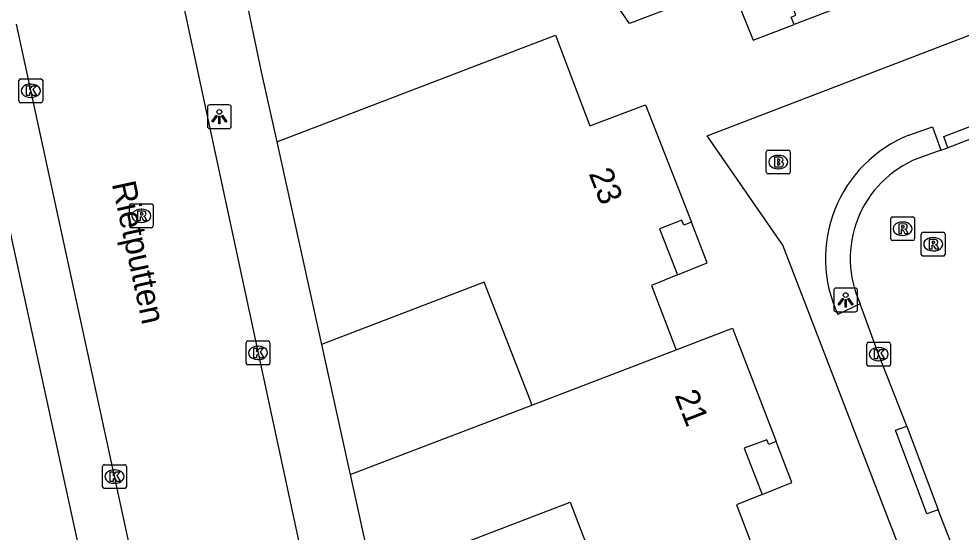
# Model space of a CAD drawing. Extents: x 159265 to 160143, y 383413 to 384319.
# Drawn here: x 159406.32 to 159445.84, y 383665.08 to 383686.61 of the extents above; entities that cross this region are included whole.
import ezdxf

# ---------------------------------------------------------------- set-up
doc = ezdxf.new("R2010")
doc.units = 0
for name, color, linetype in [('IMGEO_Brandkraan', 7, 'Continuous'), ('IMGEO_Hek', 7, 'Continuous'), ('IMGEO_Kolk', 7, 'Continuous'), ('IMGEO_Lichtpunt', 7, 'Continuous'), ('IMGEO_Openbare_ruimte_label', 7, 'Continuous'), ('IMGEO_Pand', 7, 'Continuous'), ('IMGEO_Pand_nummerreeks', 7, 'Continuous'), ('IMGEO_Pand_overbouw', 7, 'Continuous'), ('IMGEO_Rijbaan_lokaal_open', 7, 'Continuous'), ('IMGEO_Rioolput', 7, 'Continuous'), ('IMGEO_Voetpad_open', 7, 'Continuous')]:
    doc.layers.add(name, color=color, linetype=linetype)

msp = doc.modelspace()

# ---------------------------------------------------------------- linework, layer by layer
at = {"layer": 'IMGEO_Brandkraan'}
for p, q in [((159437.67, 383680.177), (159437.67, 383681.029)), ((159437.745, 383681.103), (159438.597, 383681.103)), ((159438.671, 383681.029), (159438.671, 383680.177)), ((159438.158, 383680.883), (159438.183, 383680.883)), ((159438.181, 383680.323), (159438.156, 383680.323)), ((159438.597, 383680.103), (159437.745, 383680.103))]:
    msp.add_line(p, q, dxfattribs=at)
for points in [[(159437.67, 383680.177), (159437.67, 383681.029)], [(159437.745, 383681.103), (159438.597, 383681.103)], [(159438.671, 383681.029), (159438.671, 383680.177)], [(159438.018, 383680.803), (159438.018, 383680.403), (159438.231, 383680.403)], [(159438.249, 383680.803), (159438.018, 383680.803)], [(159438.197, 383680.722), (159438.143, 383680.722), (159438.143, 383680.646)], [(159438.143, 383680.646), (159438.196, 383680.646)], [(159438.205, 383680.57), (159438.143, 383680.57), (159438.143, 383680.489)], [(159438.143, 383680.489), (159438.205, 383680.489)], [(159438.597, 383680.103), (159437.745, 383680.103)]]:
    msp.add_lwpolyline(points, dxfattribs=at)
for centre, radius, start, end in [((159437.747, 383681.027), 0.0765, 91.552, 178.448), ((159437.747, 383681.027), 0.0765, 91.552, 178.448), ((159438.595, 383681.027), 0.0765, 1.552, 88.448), ((159438.595, 383681.027), 0.0765, 1.552, 88.448), ((159438.198, 383680.684), 0.0379, 267.8285, 90.9355), ((159438.206, 383680.529), 0.0404, 269.8759, 90.5077), ((159438.253, 383680.658), 0.145, 59.4692, 91.5367), ((159438.278, 383680.705), 0.0922, 285.5137, 58.1501), ((159438.283, 383680.513), 0.105, 301.3115, 78.989), ((159437.747, 383680.179), 0.0765, 181.552, 268.448), ((159437.747, 383680.179), 0.0765, 181.552, 268.448), ((159438.237, 383680.654), 0.251, 268.6676, 293.5347), ((159438.595, 383680.179), 0.0765, 271.552, 358.448), ((159438.595, 383680.179), 0.0765, 271.552, 358.448)]:
    msp.add_arc(centre, radius, start, end, dxfattribs=at)
for centre, major_axis, ratio, start_param, end_param in [((159438.157, 383680.603), (-0.387, 0.002), 0.722429, 4.712389, 7.853982), ((159438.182, 383680.603), (-0.39, 0.002), 0.717154, 1.570796, 4.712389)]:
    msp.add_ellipse(centre, major_axis=major_axis, ratio=ratio, start_param=start_param, end_param=end_param, dxfattribs=at)
at = {"layer": 'IMGEO_Hek'}
msp.add_lwpolyline([(159419.007, 383672.947), (159420.173, 383667.674)], dxfattribs=at)
at = {"layer": 'IMGEO_Kolk'}
for p, q in [((159406.395, 383684.094), (159407.247, 383684.094)), ((159406.32, 383683.168), (159406.32, 383684.02)), ((159406.808, 383683.874), (159406.833, 383683.874)), ((159407.321, 383684.02), (159407.321, 383683.168)), ((159406.831, 383683.314), (159406.806, 383683.314)), ((159407.247, 383683.094), (159406.395, 383683.094)), ((159415.85, 383672.171), (159415.85, 383673.023)), ((159415.925, 383673.097), (159416.777, 383673.097)), ((159416.851, 383673.023), (159416.851, 383672.171)), ((159441.957, 383673.043), (159442.809, 383673.043)), ((159416.338, 383672.877), (159416.363, 383672.877)), ((159441.882, 383672.117), (159441.882, 383672.969)), ((159442.37, 383672.823), (159442.395, 383672.823)), ((159442.883, 383672.969), (159442.883, 383672.117)), ((159416.361, 383672.317), (159416.336, 383672.317)), ((159442.393, 383672.263), (159442.368, 383672.263)), ((159416.777, 383672.097), (159415.925, 383672.097)), ((159442.809, 383672.043), (159441.957, 383672.043)), ((159409.907, 383667.908), (159410.759, 383667.908)), ((159409.832, 383666.982), (159409.832, 383667.834)), ((159410.32, 383667.688), (159410.345, 383667.688)), ((159410.833, 383667.834), (159410.833, 383666.982)), ((159410.343, 383667.128), (159410.318, 383667.128)), ((159410.759, 383666.908), (159409.907, 383666.908))]:
    msp.add_line(p, q, dxfattribs=at)
for points in [[(159406.395, 383684.094), (159407.247, 383684.094)], [(159406.32, 383683.168), (159406.32, 383684.02)], [(159406.641, 383683.794), (159406.764, 383683.794), (159406.764, 383683.643), (159406.894, 383683.794), (159407.058, 383683.794), (159406.912, 383683.643), (159407.065, 383683.394), (159406.913, 383683.394), (159406.828, 383683.558), (159406.764, 383683.491), (159406.764, 383683.394), (159406.641, 383683.394), (159406.641, 383683.794)], [(159407.321, 383684.02), (159407.321, 383683.168)], [(159407.247, 383683.094), (159406.395, 383683.094)], [(159415.85, 383672.171), (159415.85, 383673.023)], [(159415.925, 383673.097), (159416.777, 383673.097)], [(159416.851, 383673.023), (159416.851, 383672.171)], [(159441.957, 383673.043), (159442.809, 383673.043)], [(159416.171, 383672.797), (159416.294, 383672.797), (159416.294, 383672.646), (159416.424, 383672.797), (159416.588, 383672.797), (159416.442, 383672.646), (159416.595, 383672.397), (159416.443, 383672.397), (159416.358, 383672.561), (159416.294, 383672.494), (159416.294, 383672.397), (159416.171, 383672.397), (159416.171, 383672.797)], [(159441.882, 383672.117), (159441.882, 383672.969)], [(159442.203, 383672.743), (159442.326, 383672.743), (159442.326, 383672.592), (159442.456, 383672.743), (159442.62, 383672.743), (159442.474, 383672.592), (159442.627, 383672.343), (159442.475, 383672.343), (159442.39, 383672.507), (159442.326, 383672.44), (159442.326, 383672.343), (159442.203, 383672.343), (159442.203, 383672.743)], [(159442.883, 383672.969), (159442.883, 383672.117)], [(159416.777, 383672.097), (159415.925, 383672.097)], [(159442.809, 383672.043), (159441.957, 383672.043)], [(159409.907, 383667.908), (159410.759, 383667.908)], [(159409.832, 383666.982), (159409.832, 383667.834)], [(159410.153, 383667.608), (159410.276, 383667.608), (159410.276, 383667.457), (159410.406, 383667.608), (159410.57, 383667.608), (159410.424, 383667.457), (159410.577, 383667.208), (159410.425, 383667.208), (159410.34, 383667.372), (159410.276, 383667.305), (159410.276, 383667.208), (159410.153, 383667.208), (159410.153, 383667.608)], [(159410.833, 383667.834), (159410.833, 383666.982)], [(159410.759, 383666.908), (159409.907, 383666.908)]]:
    msp.add_lwpolyline(points, dxfattribs=at)
for centre, start, end in [((159406.397, 383684.018), 91.552, 178.448), ((159406.397, 383684.018), 91.552, 178.448), ((159407.245, 383684.018), 1.552, 88.448), ((159407.245, 383684.018), 1.552, 88.448), ((159406.397, 383683.17), 181.552, 268.448), ((159406.397, 383683.17), 181.552, 268.448), ((159407.245, 383683.17), 271.552, 358.448), ((159407.245, 383683.17), 271.552, 358.448), ((159415.927, 383673.021), 91.552, 178.448), ((159415.927, 383673.021), 91.552, 178.448), ((159416.775, 383673.021), 1.552, 88.448), ((159416.775, 383673.021), 1.552, 88.448), ((159441.959, 383672.967), 91.552, 178.448), ((159441.959, 383672.967), 91.552, 178.448), ((159442.807, 383672.967), 1.552, 88.448), ((159442.807, 383672.967), 1.552, 88.448), ((159415.927, 383672.173), 181.552, 268.448), ((159415.927, 383672.173), 181.552, 268.448), ((159416.775, 383672.173), 271.552, 358.448), ((159416.775, 383672.173), 271.552, 358.448), ((159441.959, 383672.119), 181.552, 268.448), ((159441.959, 383672.119), 181.552, 268.448), ((159442.807, 383672.119), 271.552, 358.448), ((159442.807, 383672.119), 271.552, 358.448), ((159409.909, 383667.832), 91.552, 178.448), ((159409.909, 383667.832), 91.552, 178.448), ((159410.757, 383667.832), 1.552, 88.448), ((159410.757, 383667.832), 1.552, 88.448), ((159409.909, 383666.984), 181.552, 268.448), ((159409.909, 383666.984), 181.552, 268.448), ((159410.757, 383666.984), 271.552, 358.448), ((159410.757, 383666.984), 271.552, 358.448)]:
    msp.add_arc(centre, 0.0765, start, end, dxfattribs=at)
for centre, major_axis, ratio, start_param, end_param in [((159406.807, 383683.594), (-0.387, 0.002), 0.722429, 4.712389, 7.853982), ((159406.832, 383683.594), (-0.39, 0.002), 0.717154, 1.570796, 4.712389), ((159416.337, 383672.597), (-0.387, 0.002), 0.722429, 4.712389, 7.853982), ((159416.362, 383672.597), (-0.39, 0.002), 0.717154, 1.570796, 4.712389), ((159442.369, 383672.543), (-0.387, 0.002), 0.722429, 4.712389, 7.853982), ((159442.394, 383672.543), (-0.39, 0.002), 0.717154, 1.570796, 4.712389), ((159410.319, 383667.408), (-0.387, 0.002), 0.722429, 4.712389, 7.853982), ((159410.344, 383667.408), (-0.39, 0.002), 0.717154, 1.570796, 4.712389)]:
    msp.add_ellipse(centre, major_axis=major_axis, ratio=ratio, start_param=start_param, end_param=end_param, dxfattribs=at)
at = {"layer": 'IMGEO_Lichtpunt'}
for p, q in [((159414.231, 383682.909), (159414.231, 383682.102)), ((159414.231, 383682.909), (159414.231, 383682.102)), ((159415.133, 383683.004), (159414.325, 383683.004)), ((159415.133, 383683.004), (159414.325, 383683.004)), ((159415.227, 383682.102), (159415.227, 383682.909)), ((159415.227, 383682.102), (159415.227, 383682.909)), ((159414.325, 383682.008), (159415.133, 383682.008)), ((159414.325, 383682.008), (159415.133, 383682.008)), ((159440.499, 383675.224), (159440.499, 383674.417)), ((159440.499, 383675.224), (159440.499, 383674.417)), ((159441.401, 383675.319), (159440.593, 383675.319)), ((159441.401, 383675.319), (159440.593, 383675.319)), ((159441.495, 383674.417), (159441.495, 383675.224)), ((159441.495, 383674.417), (159441.495, 383675.224)), ((159440.593, 383674.323), (159441.401, 383674.323)), ((159440.593, 383674.323), (159441.401, 383674.323))]:
    msp.add_line(p, q, dxfattribs=at)
for points in [[(159414.605, 383682.573), (159414.644, 383682.545), (159414.456, 383682.283), (159414.418, 383682.31), (159414.605, 383682.573)], [(159414.707, 383682.525), (159414.754, 383682.525), (159414.754, 383682.203), (159414.707, 383682.203), (159414.707, 383682.525)], [(159414.817, 383682.545), (159414.855, 383682.572), (159415.042, 383682.31), (159415.003, 383682.282), (159414.817, 383682.545)], [(159440.873, 383674.888), (159440.912, 383674.86), (159440.724, 383674.598), (159440.686, 383674.625), (159440.873, 383674.888)], [(159440.975, 383674.84), (159441.022, 383674.84), (159441.022, 383674.518), (159440.975, 383674.518), (159440.975, 383674.84)], [(159441.085, 383674.86), (159441.123, 383674.887), (159441.31, 383674.625), (159441.271, 383674.597), (159441.085, 383674.86)]]:
    msp.add_lwpolyline(points, dxfattribs=at)
for centre in [(159414.73, 383682.707), (159440.998, 383675.022)]:
    msp.add_circle(centre, 0.0994, dxfattribs=at)
for centre, start, end in [((159414.325, 383682.909), 90, 180), ((159414.325, 383682.909), 90, 180), ((159415.133, 383682.909), 0, 90), ((159415.133, 383682.909), 0, 90), ((159414.325, 383682.102), 180, 270), ((159414.325, 383682.102), 180, 270), ((159415.133, 383682.102), 270, 0), ((159415.133, 383682.102), 270, 360), ((159440.593, 383675.224), 90, 180), ((159440.593, 383675.224), 90, 180), ((159441.401, 383675.224), 0, 90), ((159441.401, 383675.224), 0, 90), ((159440.593, 383674.417), 180, 270), ((159440.593, 383674.417), 180, 270), ((159441.401, 383674.417), 270, 0), ((159441.401, 383674.417), 270, 360)]:
    msp.add_arc(centre, 0.0946, start, end, dxfattribs=at)
at = {"layer": 'IMGEO_Pand'}
for points in [[(159442.676, 383690.533), (159443.581, 383688.189), (159438.836, 383686.372), (159438.712, 383686.682), (159438.913, 383686.767), (159438.557, 383687.709), (159436.62, 383686.956), (159436.185, 383688.037), (159431.935, 383686.411), (159430.379, 383688.675)], [(159417.143, 383681.455), (159428.821, 383685.925), (159430.271, 383682.125), (159432.607, 383683.008), (159434.525, 383678.084), (159434.215, 383677.96), (159434.13, 383678.161), (159433.188, 383677.806), (159433.94, 383675.868), (159432.856, 383675.429), (159433.839, 383672.869), (159433.893, 383672.729)], [(159417.143, 383681.455), (159419.007, 383672.947)], [(159427.842, 383670.411), (159427.775, 383670.584), (159425.834, 383675.56), (159419.007, 383672.947)], [(159433.893, 383672.729), (159436.245, 383673.63), (159438.084, 383668.877), (159437.774, 383668.753), (159437.689, 383668.954), (159436.747, 383668.599), (159437.499, 383666.661), (159436.415, 383666.222), (159437.398, 383663.662), (159437.464, 383663.491)], [(159427.842, 383670.411), (159433.893, 383672.729)], [(159420.214, 383667.489), (159427.842, 383670.411)], [(159420.214, 383667.489), (159421.171, 383663.166)], [(159421.171, 383663.166), (159429.445, 383666.333), (159431.346, 383661.366), (159431.416, 383661.183)]]:
    msp.add_lwpolyline(points, dxfattribs=at)
at = {"layer": 'IMGEO_Pand_overbouw'}
for points in [[(159438.712, 383686.682), (159438.913, 383686.767), (159438.557, 383687.709), (159436.62, 383686.956), (159437.12, 383685.715), (159438.836, 383686.372)], [(159434.525, 383678.084), (159434.215, 383677.96), (159434.13, 383678.161), (159433.188, 383677.806), (159433.94, 383675.868), (159435.191, 383676.375)], [(159438.084, 383668.877), (159437.774, 383668.753), (159437.689, 383668.954), (159436.747, 383668.599), (159437.499, 383666.661), (159438.746, 383667.166)]]:
    msp.add_lwpolyline(points, close=True, dxfattribs=at)
at = {"layer": 'IMGEO_Rijbaan_lokaal_open'}
for points in [[(159412.425, 383690.83), (159412.568, 383690.227), (159416.353, 383672.587), (159421.322, 383649.53)], [(159413.503, 383652.729), (159413.36, 383653.433), (159406.228, 383686.383)], [(159448.831, 383682.571), (159445.289, 383681.205)], [(159444.982, 383681.1), (159444.018, 383680.757)], [(159444.982, 383681.1), (159445.289, 383681.205)], [(159443.562, 383669.529), (159442.38, 383672.543), (159441.61, 383674.649)], [(159443.562, 383669.529), (159444.874, 383666.015)], [(159447.242, 383659.978), (159446.781, 383661.13), (159444.874, 383666.015)]]:
    msp.add_lwpolyline(points, dxfattribs=at)
msp.add_arc((159445.722, 383676.556), 4.533, 112.0827, 204.8849, dxfattribs=at)
at = {"layer": 'IMGEO_Rioolput'}
for p, q in [((159410.959, 383677.922), (159410.959, 383678.774)), ((159411.034, 383678.848), (159411.886, 383678.848)), ((159411.447, 383678.628), (159411.472, 383678.628)), ((159411.96, 383678.774), (159411.96, 383677.922)), ((159442.885, 383677.38), (159442.885, 383678.232)), ((159442.96, 383678.306), (159443.812, 383678.306)), ((159443.886, 383678.232), (159443.886, 383677.38)), ((159411.886, 383677.848), (159411.034, 383677.848)), ((159411.47, 383678.068), (159411.445, 383678.068)), ((159443.373, 383678.086), (159443.398, 383678.086)), ((159443.396, 383677.526), (159443.371, 383677.526)), ((159444.169, 383676.73), (159444.169, 383677.582)), ((159444.244, 383677.656), (159445.096, 383677.656)), ((159444.657, 383677.436), (159444.682, 383677.436)), ((159445.17, 383677.582), (159445.17, 383676.73)), ((159443.812, 383677.306), (159442.96, 383677.306)), ((159445.096, 383676.656), (159444.244, 383676.656)), ((159444.68, 383676.876), (159444.655, 383676.876))]:
    msp.add_line(p, q, dxfattribs=at)
for points in [[(159410.959, 383677.922), (159410.959, 383678.774)], [(159411.034, 383678.848), (159411.886, 383678.848)], [(159411.96, 383678.774), (159411.96, 383677.922)], [(159411.548, 383678.546), (159411.296, 383678.548), (159411.296, 383678.148)], [(159411.296, 383678.148), (159411.42, 383678.148), (159411.42, 383678.31), (159411.431, 383678.31)], [(159411.474, 383678.467), (159411.42, 383678.467), (159411.42, 383678.386)], [(159411.42, 383678.386), (159411.472, 383678.386)], [(159411.478, 383678.281), (159411.549, 383678.148), (159411.689, 383678.148), (159411.624, 383678.274)], [(159442.885, 383677.38), (159442.885, 383678.232)], [(159442.96, 383678.306), (159443.812, 383678.306)], [(159443.886, 383678.232), (159443.886, 383677.38)], [(159411.886, 383677.848), (159411.034, 383677.848)], [(159443.474, 383678.004), (159443.222, 383678.006), (159443.222, 383677.606)], [(159443.222, 383677.606), (159443.346, 383677.606), (159443.346, 383677.768), (159443.357, 383677.768)], [(159443.4, 383677.925), (159443.346, 383677.925), (159443.346, 383677.844)], [(159443.346, 383677.844), (159443.398, 383677.844)], [(159443.404, 383677.739), (159443.475, 383677.606), (159443.615, 383677.606), (159443.55, 383677.732)], [(159444.169, 383676.73), (159444.169, 383677.582)], [(159444.244, 383677.656), (159445.096, 383677.656)], [(159445.17, 383677.582), (159445.17, 383676.73)], [(159443.812, 383677.306), (159442.96, 383677.306)], [(159444.758, 383677.354), (159444.506, 383677.356), (159444.506, 383676.956)], [(159444.506, 383676.956), (159444.63, 383676.956), (159444.63, 383677.118), (159444.641, 383677.118)], [(159444.684, 383677.275), (159444.63, 383677.275), (159444.63, 383677.194)], [(159444.63, 383677.194), (159444.682, 383677.194)], [(159444.688, 383677.089), (159444.759, 383676.956), (159444.899, 383676.956), (159444.834, 383677.082)], [(159445.096, 383676.656), (159444.244, 383676.656)]]:
    msp.add_lwpolyline(points, dxfattribs=at)
for centre, radius, start, end in [((159411.036, 383678.772), 0.0765, 91.552, 178.448), ((159411.036, 383678.772), 0.0765, 91.552, 178.448), ((159411.884, 383678.772), 0.0765, 1.552, 88.448), ((159411.884, 383678.772), 0.0765, 1.552, 88.448), ((159411.43, 383678.257), 0.0533, 26.0293, 88.6989), ((159411.456, 383678.575), 0.19, 274.7715, 282.9687), ((159411.48, 383678.371), 0.0964, 77.0061, 93.1865), ((159411.494, 383678.428), 0.0378, 276.6634, 79.6772), ((159411.547, 383678.436), 0.109, 350.3612, 89.416), ((159411.545, 383678.436), 0.112, 277.5842, 350.9817), ((159411.529, 383678.221), 0.108, 29.5134, 73.7905), ((159442.962, 383678.23), 0.0765, 91.552, 178.448), ((159442.962, 383678.23), 0.0765, 91.552, 178.448), ((159443.81, 383678.23), 0.0765, 1.552, 88.448), ((159443.81, 383678.23), 0.0765, 1.552, 88.448), ((159411.036, 383677.924), 0.0765, 181.552, 268.448), ((159411.036, 383677.924), 0.0765, 181.552, 268.448), ((159411.884, 383677.924), 0.0765, 271.552, 358.448), ((159411.884, 383677.924), 0.0765, 271.552, 358.448), ((159443.356, 383677.715), 0.0533, 26.0293, 88.6989), ((159443.382, 383678.033), 0.19, 274.7715, 282.9687), ((159443.406, 383677.829), 0.0964, 77.0061, 93.1865), ((159443.42, 383677.886), 0.0378, 276.6634, 79.6772), ((159443.473, 383677.894), 0.109, 350.3612, 89.416), ((159443.471, 383677.894), 0.112, 277.5842, 350.9817), ((159443.455, 383677.679), 0.108, 29.5134, 73.7905), ((159442.962, 383677.382), 0.0765, 181.552, 268.448), ((159442.962, 383677.382), 0.0765, 181.552, 268.448), ((159443.81, 383677.382), 0.0765, 271.552, 358.448), ((159443.81, 383677.382), 0.0765, 271.552, 358.448), ((159444.246, 383677.58), 0.0765, 91.552, 178.448), ((159444.246, 383677.58), 0.0765, 91.552, 178.448), ((159445.094, 383677.58), 0.0765, 1.552, 88.448), ((159445.094, 383677.58), 0.0765, 1.552, 88.448), ((159444.64, 383677.065), 0.0533, 26.0293, 88.6989), ((159444.666, 383677.383), 0.19, 274.7715, 282.9687), ((159444.69, 383677.179), 0.0964, 77.0061, 93.1865), ((159444.704, 383677.236), 0.0378, 276.6634, 79.6772), ((159444.757, 383677.244), 0.109, 350.3612, 89.416), ((159444.755, 383677.244), 0.112, 277.5842, 350.9817), ((159444.739, 383677.029), 0.108, 29.5134, 73.7905), ((159444.246, 383676.732), 0.0765, 181.552, 268.448), ((159444.246, 383676.732), 0.0765, 181.552, 268.448), ((159445.094, 383676.732), 0.0765, 271.552, 358.448), ((159445.094, 383676.732), 0.0765, 271.552, 358.448)]:
    msp.add_arc(centre, radius, start, end, dxfattribs=at)
for centre, major_axis, ratio, start_param, end_param in [((159411.446, 383678.348), (-0.387, 0.002), 0.722429, 4.712389, 7.853982), ((159411.471, 383678.348), (-0.39, 0.002), 0.717154, 1.570796, 4.712389), ((159443.372, 383677.806), (-0.387, 0.002), 0.722429, 4.712389, 7.853982), ((159443.397, 383677.806), (-0.39, 0.002), 0.717154, 1.570796, 4.712389), ((159444.656, 383677.156), (-0.387, 0.002), 0.722429, 4.712389, 7.853982), ((159444.681, 383677.156), (-0.39, 0.002), 0.717154, 1.570796, 4.712389)]:
    msp.add_ellipse(centre, major_axis=major_axis, ratio=ratio, start_param=start_param, end_param=end_param, dxfattribs=at)
at = {"layer": 'IMGEO_Voetpad_open'}
for points in [[(159452.08, 383641.511), (159438.358, 383677.117), (159435.186, 383681.698), (159493.36, 383704.052)], [(159415.08, 383691.104), (159416.485, 383684.382), (159417.143, 383681.455)], [(159412.135, 383649.269), (159404.099, 383686.209)], [(159445.289, 383681.205), (159445.11, 383681.671), (159448.652, 383683.037), (159448.831, 383682.571)], [(159443.649, 383681.73), (159444.633, 383682.08), (159444.982, 383681.1)], [(159441.61, 383674.649), (159440.667, 383674.211)], [(159419.007, 383672.947), (159420.173, 383667.674), (159420.214, 383667.489)], [(159444.874, 383666.015), (159444.406, 383665.841), (159443.094, 383669.355), (159443.562, 383669.529)]]:
    msp.add_lwpolyline(points, dxfattribs=at)
msp.add_arc((159445.724, 383676.556), 5.574, 111.8501, 204.8838, dxfattribs=at)

# ---------------------------------------------------------------- texts
at = {"layer": 'IMGEO_Openbare_ruimte_label'}
msp.add_text('Rietputten', height=1, rotation=282.2429, dxfattribs=at).set_placement((159410.215, 383679.695))
at = {"layer": 'IMGEO_Pand_nummerreeks'}
for s, rotation, p in [('23', 291.2794, (159430.21, 383680.125)), ('21', 291.1534, (159433.814, 383670.825))]:
    msp.add_text(s, height=1, rotation=rotation, dxfattribs=at).set_placement(p)

doc.saveas('drawing.dxf')
